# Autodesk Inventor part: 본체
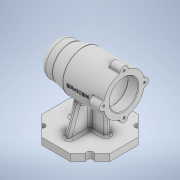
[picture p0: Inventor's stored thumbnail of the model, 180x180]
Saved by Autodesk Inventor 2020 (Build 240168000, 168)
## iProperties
Created: 2021-01
Part Number: 본체
Material: 일반
Document SubType Name: Modeling
Designer: PC2-15
Density: 1 g/cm^3
Appearance: 기본값
Author: PC2-15
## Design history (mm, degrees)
sketch "스케치1"
  geometry: L1 (-50, -20.711)-(-50, 20.711); L2 (-50, 20.711)-(-20.711, 50); L3 (-20.711, 50)-(20.711, 50); L4 (20.711, 50)-(50, 20.711); L5 (50, 20.711)-(50, -20.711); L6 (50, -20.711)-(20.711, -50); L7 (20.711, -50)-(-20.711, -50); L8 (-20.711, -50)-(-50, -20.711); 3 further points
  constraints: 16 end point, 1 coincident, 1 midpoint, 1 vertical alignment, 17 other
  dimensions: "d0" = 50 horizontal distance of L1.start point (0, -50)
extrude "돌출1" new body sketch "스케치1" distance "d1" = 10; taper "d2" = 0 deg
sketch "스케치2"
  geometry: L1 (50, 20.711)-(20.711, 50) reference; L2 (0, 0)-(35.355, 35.355); C1 r 4.5 at (35.355, 35.355); 1 further point
  constraints: 2 coincident, 2 end point, 1 centre point, 1 midpoint, 4 other
  dimensions: "d3" = 9 diameter of C1
extrude "돌출2" cut sketch "스케치2" distance "d4" = 10; taper "d5" = 0 deg
node "작업 평면1"
sketch "스케치3"
  geometry: C1 r 30 at (75, 0); 1 further point
  constraints: 1 centre point, 1 horizontal alignment
  dimensions: "d10" = 60 diameter of C1; "d11" = 75 distance of point (0, 0) C1.centre
extrude "돌출3" join sketch "스케치3" distance "d12" = 60; taper "d13" = 0 deg
sketch "스케치4"
  geometry: L1 (-10, 45)-(-10, 105) reference; L2 (-10, 105)-(-30, 100); L3 (-30, 100)-(-50, 100); L4 (-50, 100)-(-50, 75); L5 (-10, 75)-(-50, 75); 1 further point
  constraints: 8 end point, 2 horizontal, 1 midpoint, 1 perpendicular
  dimensions: "d14" = 40 distance from line of L1.end L4; "d15" = 20 distance from line of L2.end L4; "d16" = 50 diameter of L3 L5
revolve "회전1" sketch "스케치4" stored, may be unused: angle "d17" = 90 deg
sketch "스케치5"
  geometry: C1 r 6 at (30, 0); A1 r 6 centre (0, 30) between (5.97, 29.4) and (-5.97, 29.4); A2 r 6 centre (0, -30) between (-5.97, -29.4) and (5.97, -29.4); A3 r 6 centre (-30, 0) between (-29.4, 5.97) and (-29.4, -5.97); 4 further points
  constraints: 6 point on circle, 4 centre point, 2 horizontal alignment, 2 vertical alignment, 11 other
  dimensions: "d18" = 12 diameter of A1; "d19" = 12 diameter of C1; "d20" = 12 diameter of A2; "d22" = 12 diameter of A3
extrude "돌출4" join sketch "스케치5" distance "d23" = 16; taper "d24" = 0 deg
sketch "스케치6"
  geometry: L1 (-10, 45)-(-10, 105) reference; L2 (50, 69.03)-(34, 69.03) reference; L3 (34, 69.03)-(34, 80.97) reference; L4 (34, 80.97)-(50, 80.97) reference; L5 (50, 104.4)-(50, 80.97) reference; L6 (50, 104.4)-(34, 104.4) reference; L7 (34, 104.4)-(34, 104.4) reference; L8 (34, 104.4)-(50, 104.4) reference; L9 (50, 80.97)-(50, 104.4) reference; L10 (50, 80.97)-(34, 80.97) reference; L11 (34, 80.97)-(34, 69.03) reference; L12 (34, 69.03)-(50, 69.03) reference; L13 (50, 45.6)-(50, 69.03) reference; L14 (50, 45.6)-(34, 45.6) reference; L15 (34, 45.6)-(34, 45.6) reference; L16 (34, 45.6)-(50, 45.6) reference; L17 (50, 69.03)-(50, 45.6) reference; L18 (50, 69)-(50, 81) reference; L19 (50, 75)-(-36.955, 75); L20 (50, 80.97)-(50, 104.4) reference; L21 (50, 96)-(35, 96); L22 (35, 96)-(35, 99); L23 (35, 99)-(-7, 99); L24 (-7, 99)-(-7, 96); L25 (-7, 96)-(-19, 96); L26 (-19, 96)-(-19, 75); 2 further points
  constraints: 14 end point, 6 perpendicular, 2 point on line, 1 midpoint, 1 vertical
  dimensions: "d25" = 42 diameter of L21 L19; "d26" = 15 distance of L21.start L21.end; "d27" = 48 diameter of L23 L19; "d28" = 42 distance of L22.end L23.end; "d29" = 12 distance of L24.end L25.end; "d30" = 42 diameter of L25 L19
revolve "회전2" sketch "스케치6" stored, may be unused: angle "d31" = 90 deg
sketch "스케치7"
  geometry: L1 (-19, 54)-(-19, 96) reference; L2 (-19, 75)-(-50, 75); L3 (-50, 50)-(-50, 100) reference; L4 (-19, 92.5)-(-37, 92.5); L5 (-37, 92.5)-(-37, 91); L6 (-37, 91)-(-41, 91); L7 (-41, 91)-(-41, 85.5); L8 (-41, 85.5)-(-44, 85.5); L9 (-44, 85.5)-(-44, 75); 1 further point
  constraints: 14 end point, 4 perpendicular, 2 midpoint, 2 point on line, 1 horizontal, 1 vertical
  dimensions: "d32" = 18 distance of L4.start L4.end; "d33" = 35 diameter of L4 L2; "d34" = 4 distance of L5.end L6.end; "d35" = 32 diameter of L6 L2; "d36" = 3 distance of L7.end L8.end; "d37" = 21 diameter of L8 L2
revolve "회전3" sketch "스케치7" stored, may be unused: angle "d38" = 90 deg
sketch "스케치10"
  geometry: L1 (10, -20.711)-(10, 20.711) reference; L2 (10, 38.537)-(10, 30.855) reference; L3 (10, 20.711)-(10, 32.173) reference; L4 (10, -32.173)-(10, -20.711) reference; L5 (10, -30.855)-(10, -38.537) reference; L6 (52.293, 19.606)-(10, 35); L7 (52.293, -19.606)-(10, -35); L8 (0, 50)-(10, 50) reference; L9 (0, -50)-(10, -50) reference; L10 (10, 38.537)-(10, 50) reference; A1 r 30 centre (75, 0) between (52.293, 19.606) and (52.293, -19.606) reference; 1 further point
  constraints: 4 end point, 2 point on circle, 2 point on line
  dimensions: "d45" = 15 distance from line of L6.end L8; "d46" = 15 distance from line of L9 L7.end; "d47" = 110 deg angle of L6 L10; "d48" = 110 deg angle of L5 L7
extrude "돌출6" join sketch "스케치10" stored distance "d49" = 8; taper "d50" = 0 deg
fillet "모깎기11" dims "d104" = 3
sketch "스케치12"
  geometry: L1 (-30, 50)-(-10, 45) reference; L2 (-10, 45)-(34, 45) reference; L3 (-38.537, 10)-(-30.855, 10) reference; L4 (-20.711, 10)-(-32.173, 10) reference; L5 (20.711, 10)-(-20.711, 10) reference; L6 (-19.724, 47.431)-(-27, 10); L7 (-50, 0)-(-50, 10) reference; L8 (-38.537, 10)-(-50, 10) reference; L9 (-19.724, 47.431)-(-10, 45); L10 (-4, 52.293)-(-4, 10) reference; L11 (-4, 45)-(-4, 10); L12 (-4, 10)-(-27, 10); L13 (-10, 45)-(-4, 45); 1 further point
  constraints: 10 end point, 4 point on line, 1 collinear, 1 perpendicular
  dimensions: "d54" = 23 distance from line of L6.end L7; "d55" = 101 deg angle of L6 L8
feature "리브1" sketch "스케치12" dims "d56" = 1, "d57" = 8, "d58" = 0, "d59" = 0, "d60" = 1, "d61" = 1
node "작업 평면2"
sketch "스케치14"
  geometry: L1 (-18, 85)-(42, 85); L2 (42, 85)-(42, 65); L3 (42, 65)-(-18, 65); L4 (-18, 65)-(-18, 85); L5 (-18, 75)-(42, 75); L6 (12, 85)-(12, 65); L7 (50, 80.97)-(50, 104.4) reference; L8 (-20.711, 0)-(20.711, 0) reference; 1 further point
  constraints: 4 end point, 4 midpoint, 2 other
  dimensions: "d105" = 60 distance between parallel lines of L2 L4; "d106" = 20 distance between parallel lines of L3 L1; "d107" = 38 distance between parallel lines of L7 L6; "d108" = 75 distance between parallel lines of L5 L8
fillet "모깎기1" dims "d63" = 10
fillet "모깎기2" dims "d70" = 0.3
fillet "모깎기3" dims "d71" = 3
chamfer "모따기3" distance "d72" = 1; stored, may be unused: second distance "d73" = 2, angle "d74" = 45 deg
fillet "모깎기4" dims "d75" = 3
sketch "스케치16"
  geometry: A1 r 6 centre (0, 105) between (5.97, 104.4) and (-5.97, 104.4) reference; 2 further points
  constraints: 1 coincident
hole "구멍1" sketch "스케치16" at (0, 105) diameter "d76" = 3.242; stored, may be unused: countersink angle "d80" = 90 deg, drill point angle "d82" = 118 deg; dims "d77" = 8, "d78" = 4, "d79" = 2, "d81" = 10
fillet "모깎기5" dims "d86" = 1
fillet "모깎기6" dims "d87" = 1
sketch "스케치17"
  geometry: L1 (27, 10)-(27, 37.964); L2 (50, 0)-(50, 10) reference; 1 further point
  constraints: 2 end point, 1 vertical
  dimensions: "d94" = 23 distance between parallel lines of L1 L2
feature "리브2" sketch "스케치17" dims "d95" = 1, "d96" = 8, "d97" = 0, "d98" = 0, "d99" = 1, "d100" = 1
fillet "모깎기8" dims "d101" = 3
fillet "모깎기9" dims "d102" = 3
fillet "모깎기10" dims "d103" = 3
feature "엠보싱2" dims "d109" = 0.5, "d110" = 0
node "솔리드1"
pattern_circular "원형 패턴1" dims angle "d7" = 360 deg
pattern_circular "원형 패턴2" dims angle "d84" = 360 deg
pattern_circular "원형 패턴3" dims angle "d89" = 360 deg
node "투영된 루프1"
other parameters: "d62" = 86.75
